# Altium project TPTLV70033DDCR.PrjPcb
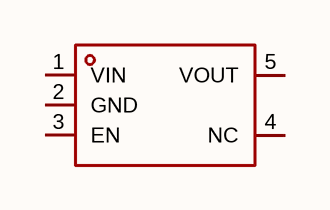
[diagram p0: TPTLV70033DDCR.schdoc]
1 sheet, 1 parts. Net scope: global (net labels, ports and power ports of the same name join across sheets).

## Sheet TPTLV70033DDCR.schdoc
size 127 x 101 mm

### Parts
U?  tptlv70033ddcr  [SOT-23-5_L2.9-W1.6-P0.95-LS2.8-BL]  (value not drawn)

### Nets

Not connected (* = marked no-connect by the designer): U? 1(VIN) 2(GND) 3(EN) 4(NC) 5(VOUT)

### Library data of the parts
U? = tptlv70033ddcr: 输出极性:正极;工作电压:5.5V;输出电压:3.3V;输出电流:300mA;电源纹波抑制比(PSRR):75dB@(1kHz);输出类型:固定;; Manufacturer: TECH PUBLIC(台舟); AddInBom: yes; ModelId: 018c57e721114987ae90467fe9f1d259; ModelTransform: 114.96,110.236,0,0,0,0,0,0,0; Output Configuration: 正极; Voltage - Supply: 5.5V; Output Voltage: 3.3V; Output Current: 300mA; Voltage Dropout: 200mV@(300mA); standby current: 20uA; Noise: 51uVrms; Output Type: 固定; Number of Outputs: 1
